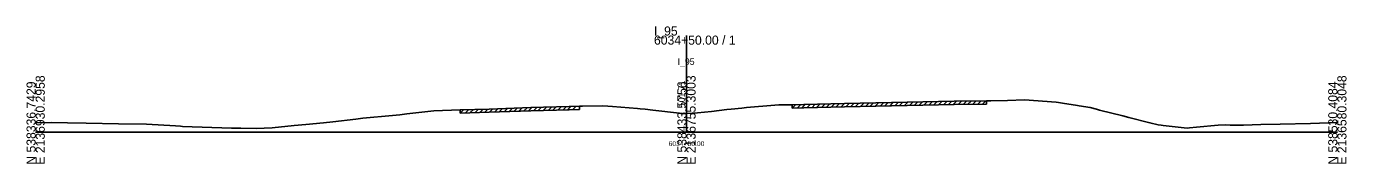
# Model space of a CAD drawing. Extents: x -12534 to 3403, y -1332 to 21983.
# Drawn here: x 997.2 to 1402.8, y 19490.3 to 19532.6 of the extents above; entities that cross this region are included whole.
import ezdxf

# ---------------------------------------------------------------- set-up
doc = ezdxf.new("R2010")
doc.units = 0
for name, color, linetype in [('RD_GPK_XS_Cell', 7, 'Continuous'), ('RD_XS_ExGround', 7, 'Continuous'), ('RD_XS_ExPaveRet', 7, 'Continuous'), ('RD_XS_TX_Baseline', 7, 'Continuous'), ('RD_XS_TX_Elev_EX', 7, 'Continuous'), ('RD_XS_TX_Station', 7, 'Continuous')]:
    doc.layers.add(name, color=color, linetype=linetype)

msp = doc.modelspace()

# ---------------------------------------------------------------- linework, layer by layer
at = {"layer": 'RD_GPK_XS_Cell'}
for p, q in [((1200, 19500), (1200, 19529.74)), ((1000, 19500), (1200, 19500)), ((1200, 19500), (1400, 19500))]:
    msp.add_line(p, q, dxfattribs=at)
at = {"layer": 'RD_XS_ExGround'}
msp.add_lwpolyline([(1000, 19502.92), (1005.01, 19502.95), (1009.77, 19502.88), (1015.55, 19502.82), (1025.43, 19502.61), (1034.08, 19502.5), (1042.99, 19501.97), (1044.48, 19501.85), (1045.17, 19501.79), (1060.14, 19501.2), (1063.02, 19501.2), (1067.75, 19501.16), (1072.7, 19501.38), (1079.48, 19502.07), (1083.05, 19502.39), (1088.49, 19502.87), (1091.35, 19503.18), (1098.39, 19504.03), (1100.58, 19504.27), (1103.97, 19504.64), (1106.3, 19504.8), (1111.87, 19505.35), (1114.11, 19505.6), (1122.35, 19506.52), (1130.46, 19506.83), (1139.4, 19507.12), (1152.14, 19507.58), (1163.94, 19507.87), (1167.08, 19507.99), (1168.08, 19508.04), (1174.12, 19508.06), (1175.87, 19507.99), (1177.3, 19507.87), (1184.93, 19507.3), (1185.8, 19507.18), (1187.25, 19507.08), (1189.69, 19506.75), (1197.89, 19505.87), (1199.6, 19505.68), (1200, 19505.71), (1203.35, 19505.95), (1207.7, 19506.32), (1212.41, 19506.95), (1213.72, 19507.08), (1217.01, 19507.43), (1218.46, 19507.59), (1227.12, 19508.33), (1228.4, 19508.44), (1228.76, 19508.46), (1232.48, 19508.38), (1236.07, 19508.47), (1248.51, 19508.82), (1282.2, 19509.51), (1292.18, 19509.64), (1293.48, 19509.62), (1298.66, 19509.72), (1303.84, 19509.91), (1313.56, 19509.24), (1314.31, 19509.17), (1315.58, 19508.96), (1320.11, 19508.22), (1320.71, 19508.15), (1324.04, 19507.64), (1325.98, 19507.03), (1326.86, 19506.78), (1334.03, 19505), (1335.93, 19504.5), (1342.38, 19502.92), (1344.94, 19502.29), (1345.87, 19502.11), (1346.47, 19502.08), (1353.84, 19501.27), (1354.53, 19501.29), (1356.76, 19501.52), (1363.36, 19502.11), (1365.49, 19502.25), (1367.06, 19502.13), (1371.19, 19502.16), (1376.44, 19502.33), (1382.4, 19502.49), (1391.71, 19502.69), (1400, 19502.97)], dxfattribs=at)
at = {"layer": 'RD_XS_ExPaveRet'}
for p, q in [((1268.48, 19508.23), (1269.5, 19509.25)), ((1269.98, 19508.26), (1271, 19509.28)), ((1271.48, 19508.29), (1272.5, 19509.31)), ((1272.98, 19508.32), (1274, 19509.34)), ((1274.48, 19508.35), (1275.5, 19509.37)), ((1275.98, 19508.38), (1277, 19509.4)), ((1277.48, 19508.41), (1278.5, 19509.43)), ((1278.98, 19508.44), (1280, 19509.47)), ((1280.48, 19508.47), (1281.5, 19509.5)), ((1281.98, 19508.51), (1283, 19509.52)), ((1283.48, 19508.53), (1284.5, 19509.54)), ((1284.98, 19508.55), (1286, 19509.56)), ((1286.48, 19508.57), (1287.5, 19509.58)), ((1287.98, 19508.59), (1289, 19509.6)), ((1289.48, 19508.61), (1290.5, 19509.62)), ((1290.98, 19508.63), (1292, 19509.64)), ((1292.18, 19509.64), (1292.18, 19508.64)), ((1130.46, 19505.83), (1131.5, 19506.86)), ((1130.46, 19505.83), (1130.46, 19506.83)), ((1130.46, 19505.83), (1139.4, 19506.12)), ((1131.96, 19505.88), (1133, 19506.91)), ((1133.46, 19505.93), (1134.5, 19506.96)), ((1134.96, 19505.98), (1136, 19507.01)), ((1136.46, 19506.03), (1137.5, 19507.06)), ((1137.96, 19506.07), (1139, 19507.11)), ((1139.4, 19506.12), (1152.14, 19506.58)), ((1139.46, 19506.12), (1140.5, 19507.16)), ((1140.96, 19506.18), (1142, 19507.22)), ((1142.46, 19506.23), (1143.5, 19507.27)), ((1143.96, 19506.29), (1145, 19507.32)), ((1145.46, 19506.34), (1146.5, 19507.38)), ((1146.96, 19506.39), (1148, 19507.43)), ((1148.46, 19506.45), (1149.5, 19507.49)), ((1149.96, 19506.5), (1151, 19507.54)), ((1151.46, 19506.56), (1152.5, 19507.59)), ((1152.14, 19506.58), (1163.94, 19506.87)), ((1152.96, 19506.6), (1153.99, 19507.63)), ((1154.46, 19506.64), (1155.49, 19507.66)), ((1155.96, 19506.68), (1156.99, 19507.7)), ((1157.46, 19506.71), (1158.49, 19507.74)), ((1158.96, 19506.75), (1159.99, 19507.77)), ((1160.46, 19506.79), (1161.49, 19507.81)), ((1161.96, 19506.82), (1162.99, 19507.85)), ((1163.46, 19506.86), (1164.49, 19507.89)), ((1163.94, 19506.87), (1167.08, 19506.99)), ((1164.96, 19506.91), (1166, 19507.95)), ((1167.08, 19507.99), (1167.08, 19506.99)), ((1232.48, 19507.38), (1233.51, 19508.4)), ((1232.48, 19507.38), (1232.48, 19508.38)), ((1232.48, 19507.38), (1236.07, 19507.47)), ((1233.98, 19507.42), (1235.01, 19508.44)), ((1235.48, 19507.46), (1236.51, 19508.48)), ((1236.07, 19507.47), (1248.51, 19507.82)), ((1236.98, 19507.5), (1238.01, 19508.53)), ((1238.48, 19507.54), (1239.51, 19508.57)), ((1239.98, 19507.58), (1241.01, 19508.61)), ((1241.48, 19507.62), (1242.51, 19508.65)), ((1242.98, 19507.66), (1244.01, 19508.69)), ((1244.48, 19507.71), (1245.51, 19508.74)), ((1245.98, 19507.75), (1247.01, 19508.78)), ((1247.48, 19507.79), (1248.51, 19508.82)), ((1248.51, 19507.82), (1282.2, 19508.51)), ((1248.98, 19507.83), (1250, 19508.85)), ((1250.48, 19507.86), (1251.5, 19508.88)), ((1251.98, 19507.89), (1253, 19508.91)), ((1253.48, 19507.92), (1254.5, 19508.94)), ((1254.98, 19507.95), (1256, 19508.97)), ((1256.48, 19507.98), (1257.5, 19509)), ((1257.98, 19508.01), (1259, 19509.03)), ((1259.48, 19508.04), (1260.5, 19509.07)), ((1260.98, 19508.08), (1262, 19509.1)), ((1262.48, 19508.11), (1263.5, 19509.13)), ((1263.98, 19508.14), (1265, 19509.16)), ((1265.48, 19508.17), (1266.5, 19509.19)), ((1266.98, 19508.2), (1268, 19509.22)), ((1282.2, 19508.51), (1292.18, 19508.64))]:
    msp.add_line(p, q, dxfattribs=at)

# ---------------------------------------------------------------- texts
at = {"layer": 'RD_GPK_XS_Cell'}
for s, p in [('6034+50.00 / 1', (1190, 19526.94)), ('I_95', (1190, 19529.74))]:
    msp.add_text(s, height=2.8, dxfattribs=at).set_placement(p)
for s, p in [('N 538336.7429', (1000, 19490)), ('E 2136930.2958', (1002.8, 19490)), ('N 538433.5756', (1200, 19490)), ('E 2136755.3003', (1202.8, 19490)), ('N 538530.4084', (1400, 19490)), ('E 2136580.3048', (1402.8, 19490))]:
    msp.add_text(s, height=2.8, rotation=90, dxfattribs=at).set_placement(p)
at = {"layer": 'RD_XS_TX_Baseline'}
msp.add_text('I_95', height=2, dxfattribs=at).set_placement((1197.28, 19520.71))
at = {"layer": 'RD_XS_TX_Elev_EX'}
msp.add_text('101.71', height=2, rotation=90, dxfattribs=at).set_placement((1199.5, 19507.71))
at = {"layer": 'RD_XS_TX_Station'}
msp.add_text('6034+50.00', height=1.5, dxfattribs=at).set_placement((1194.5, 19495.71))

doc.saveas('drawing.dxf')
